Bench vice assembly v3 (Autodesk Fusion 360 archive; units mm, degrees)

design "Bench vice assembly" references "SCREW 2", "Base Plate"
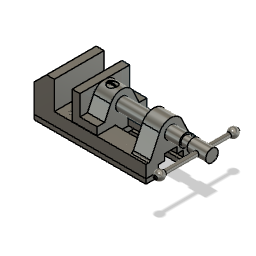
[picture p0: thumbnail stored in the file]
sketch "Sketch1" plane through (0, 0, 0) normal (0, 0, 1) x axis (1, 0, 0)
  line L1 (0, 36) -> (0, 0)
  line L2 (16, 52) -> (0, 36)
  line L3 (26, 52) -> (16, 52)
  line L4 (26, 16) -> (26, 52)
  line L5 (144, 16) -> (26, 16)
  line L6 (144, 0) -> (144, 16)
  line L7 (0, 0) -> (144, 0)
  point P1 (0, 0)
  point P2 (0, 0)
  point P10 (0, 0)
  point P7 (144, 16)
  point P8 (144, 16)
  point P9 (144, 0)
  point P4 (16, 52)
  point P5 (26, 52)
  point P3 (0, 36)
  coincident P1 P2
  vertical L1
  horizontal L3
  perpendicular L3 L4
  perpendicular L4 L5
  coincident P1 P10
  horizontal L7
  vertical L6
  coincident P7 P8
  dimension "d1" distance P9 P10 = 144
  dimension "d3" distance L5 L7 = 16
  dimension "d4" distance P4 P5 = 10
  dimension "d5" distance P3 P4 = 16
  dimension "d6" distance P3 P4 = 16
  dimension "d16" distance L3 L5 = 36
  dimension "d52" OffsetX = 0
  dimension "d53" OffsetY = 0
  dimension "d54" OffsetZ = 0
  dimension "d55" AngleZ = 0
  dimension "d43" OffsetX = 0
  dimension "d44" OffsetY = 0
  dimension "d45" OffsetZ = 0
  dimension "d46" AngleZ = 0
extrude "Extrude1" new body sketch "Sketch1" along normal blind 64 and against normal blind 0
sketch "Sketch2" plane through (144, 0, 0) normal (1, 0, 0) x axis (0, 0, -1)
  line L1 (0, 16) -> (0, 0)
  line L2 (-64, 16) -> (0, 16)
  line L3 (-64, 0) -> (-64, 16)
  line L4 (0, 0) -> (-64, 0)
  line L5 (-46.5009, 42.7619) -> (-58.9802, 16)
  line L6 (-5.0198, 16) -> (-17.4991, 42.7619)
  line L7 (-5.0198, 16) -> (-58.9802, 16)
  line L8 (-32, 59.4382) -> (-32, 0)
  arc A1 centre (-32, 36) radius 16 clockwise from (-46.5009, 42.7619) to (-17.4991, 42.7619)
  circle C1 centre (-32, 36) radius 8
  point P6 (-58.9802, 16)
  point P10 (-5.0198, 16)
  point P11 (-32, 0)
  point P9 (-32, 36)
  coincident L2 P6
  tangent L5 A1
  coincident L2 P10
  tangent A1 L6
  midpoint L4 P11
  perpendicular L4 L8
  symmetric L5 L6 L8
  concentric A1 C1
  dimension "d12" radius A1 = 16
  dimension "d13" angle L5 L6 = 50
  dimension "d14" distance L4 P9 = 36
  dimension "d15" diameter C1 = 16
extrude "Extrude2" add sketch "Sketch2" profile of L2 L5 A1 L6 L7 C1 against normal blind 22
fillet "Fillet1" radius 3
sketch "Sketch3" plane through (144, 0, 0) normal (1, 0, 0) x axis (0, 0, -1)
  line L1 (0, 16) -> (0, 0)
  line L2 (-3.1086, 16) -> (0, 16)
  line L3 (-17.4991, 42.7619) -> (-5.8275, 17.7321)
  line L4 (-58.1725, 17.7321) -> (-46.5009, 42.7619)
  line L5 (-64, 16) -> (-60.8914, 16)
  line L6 (-64, 0) -> (-64, 16)
  line L7 (0, 0) -> (-64, 0)
  line L8 (-48, 8) -> (-48, 0)
  line L9 (-40, 8) -> (-48, 8)
  line L10 (-64, 16) -> (0, 16)
  line L11 (-40, 16) -> (-40, 8)
  line L12 (-3.1086, 16) -> (-60.8914, 16)
  line L13 (-24, 8) -> (-24, 16)
  line L14 (-16, 8) -> (-24, 8)
  line L15 (-16, 0) -> (-16, 8)
  line L16 (-16, 0) -> (-48, 0)
  line L17 (-32, 74.8172) -> (-32, 0)
  line L18 (-24, 16) -> (-40, 16)
  circle C1 centre (-32, 36) radius 8
  arc A1 centre (-3.1086, 19) radius 3 clockwise from (-3.1086, 16) to (-5.8275, 17.7321)
  arc A2 centre (-32, 36) radius 16 clockwise from (-46.5009, 42.7619) to (-17.4991, 42.7619)
  arc A3 centre (-60.8914, 19) radius 3 clockwise from (-58.1725, 17.7321) to (-60.8914, 16)
  point P15 (-48, 0)
  point P20 (-40, 16)
  point P23 (-24, 16)
  point P26 (-16, 0)
  point P27 (-32, 0)
  coincident L7 P15
  perpendicular L7 L8
  perpendicular L8 L9
  coincident L10 P20
  perpendicular L7 L11
  coincident L10 P23
  perpendicular L10 L13
  perpendicular L13 L14
  coincident L7 P26
  midpoint L7 P27
  perpendicular L16 L17
  vertical L15
  symmetric L8 L15 L17
  symmetric L11 L13 L17
  dimension "d21" distance L11 L13 = 16
  dimension "d22" distance L8 L15 = 32
extrude "Extrude3" cut sketch "Sketch3" profile of L7 L8 L9 L10 L11 L12 L13 L14 L15 L16 L18 no distance stored
hole "Hole1" HoleDepth 10 HoleDiameter 6 TipAngle 118 RefDim1 10 RefDim2 36
hole "Hole3" HoleDepth 8 HoleDiameter 6 TipAngle 118
hole "Hole5" HoleDepth 10 HoleDiameter 6 TipAngle 118 RefDim1 38 RefDim2 10
sketch "Sketch5" plane through (0, 16, 0) normal (0, 1, 0) x axis (-1, 0, 0)
  line L1 (-122, 24) -> (-26, 24)
  line L2 (-122, 3.1086) -> (-122, 24)
  line L3 (-144, 3.1086) -> (-122, 3.1086)
  line L4 (-144, 0) -> (-144, 3.1086)
  line L5 (-26, 0) -> (-144, 0)
  line L6 (-26, 24) -> (-26, 0)
hole "Hole6" HoleDepth 8 HoleDiameter 6 TipAngle 118 RefDim1 38 RefDim2 10
ground "Ground1"
sketch "Sketch1" plane through (0, 0, 0) normal (0, 0, 1) x axis (1, 0, 0)
  line L1 (0, 10) -> (0, 0)
  line L2 (22, 10) -> (0, 10)
  line L3 (22, 36) -> (22, 10)
  line L4 (32, 36) -> (22, 36)
  line L5 (32, 0) -> (32, 36)
  line L6 (0, 0) -> (32, 0)
  point P1 (0, 0)
  point P2 (0, 0)
  point P3 (0, 10)
  point P5 (22, 36)
  point P6 (32, 36)
  coincident P1 P2
  vertical L1
  perpendicular L1 L2
  perpendicular L2 L3
  perpendicular L3 L4
  perpendicular L2 L5
  horizontal L6
  dimension "d1_1" distance P2 P3 = 10
  dimension "d2" distance P5 P6 = 10
  dimension "d3_1" distance L4 L6 = 36
  dimension "d4_1" distance L1 L5 = 32
  dimension "d30" OffsetX = 0
  dimension "d31" OffsetY = 0
  dimension "d41" OffsetZ = 0
  dimension "d42" AngleZ = 0
extrude "Extrude1" new body sketch "Sketch1" distance 64 named "d5_1"
sketch "Sketch2" plane through (0, 0, 32) normal (0, 0, 1) x axis (1, 0, 0)
  line L1 (32, 36) -> (32, 0)
  line L2 (22, 36) -> (32, 36)
  line L3 (22, 10) -> (22, 36)
  line L4 (0, 10) -> (22, 10)
  line L5 (0, 0) -> (0, 10)
  line L6 (32, 0) -> (0, 0)
sketch "Sketch3" plane through (0, 0, 0) normal (-1, 0, 0) x axis (0, 0, 1)
  line L1 (32, 0) -> (-32, 0)
  line L2 (32, 10) -> (32, 0)
  line L3 (-32, 0) -> (-32, 10)
  line L4 (-32, 10) -> (-32, 0)
  line L5 (-14.5009, 26.7619) -> (-22.3171, 10)
  line L6 (22.3171, 10) -> (14.5009, 26.7619)
  line L7 (32, 10) -> (22.3171, 10)
  line L8 (32, 10) -> (32, 0)
  line L9 (-32, 10) -> (-22.3171, 10)
  line L10 (32, 10) -> (-32, 10)
  line L11 (0, 44.7994) -> (0, 0)
  arc A1 centre (0, 20) radius 16 clockwise from (-14.5009, 26.7619) to (14.5009, 26.7619)
  point P3 (32, 0)
  point P15 (32, 0)
  point P2 (-32, 0)
  point P16 (-32, 0)
  point P8 (-22.3171, 10)
  point P12 (22.3171, 10)
  point P1 (0, 0)
  point P17 (0, 0)
  tangent L5 A1
  perpendicular L4 L9
  tangent A1 L6
  coincident P3 P15
  coincident P2 P16
  coincident P8 L10
  coincident P12 L10
  coincident P1 P17
  perpendicular L1 L11
  symmetric L5 L6 L11
  dimension "d7" angle L5 L6 = 50
  dimension "d8_1" radius A1 = 16
extrude "Extrude2" add sketch "Sketch3" profile of L5 A1 L6 L10 against normal blind 22 named "d9_1"
sketch "Sketch4" plane through (0, 0, 0) normal (-1, 0, 0) x axis (0, 0, 1)
  line L1 (32, 0) -> (-32, 0)
  line L2 (32, 10) -> (32, 0)
  line L3 (22.3171, 10) -> (32, 10)
  line L4 (14.5009, 26.7619) -> (22.3171, 10)
  line L5 (-22.3171, 10) -> (-14.5009, 26.7619)
  line L6 (-32, 10) -> (-22.3171, 10)
  line L7 (-32, 0) -> (-32, 10)
  line L8 (8, 0) -> (-8, 0)
  line L9 (8, -9) -> (8, 0)
  line L10 (-8, -9) -> (8, -9)
  line L11 (-8, 0) -> (-8, -9)
  line L12 (0, 61.8618) -> (0, 0)
  arc A1 centre (0, 20) radius 16 clockwise from (-14.5009, 26.7619) to (14.5009, 26.7619)
  point P11 (-8, 0)
  point P1 (0, 0)
  point P15 (0, 0)
  point P13 (8, -9)
  point P14 (-8, -9)
  horizontal L8
  vertical L9
  horizontal L10
  vertical L11
  coincident L1 P11
  coincident P1 P15
  vertical L12
  symmetric L9 L11 L12
  dimension "d11_1" distance P13 P14 = 16
  dimension "d12_1" distance L8 L10 = 9
extrude "Extrude3" add sketch "Sketch4" profile of L1 L8 L9 L10 L11 against normal blind 32 named "d13_1"
hole "Hole2" HoleDepth 16 HoleDiameter 6 named "d21_1" TipAngle 118 named "d22_1" RefDim1 8 named "d23_1" RefDim2 8
hole "Hole3" HoleDepth 16 HoleDiameter 6 TipAngle 118 RefDim1 8 RefDim2 8
sketch "Sketch5" plane through (0, 0, 0) normal (-1, 0, 0) x axis (0, 0, 1)
  line L1 (-8, 0) -> (-32, 0)
  line L2 (-8, -9) -> (-8, 0)
  line L3 (8, -9) -> (-8, -9)
  line L4 (8, 0) -> (8, -9)
  line L5 (32, 0) -> (8, 0)
  line L6 (32, 10) -> (32, 0)
  line L7 (22.3171, 10) -> (32, 10)
  line L8 (14.5009, 26.7619) -> (22.3171, 10)
  line L9 (-22.3171, 10) -> (-14.5009, 26.7619)
  line L10 (-32, 10) -> (-22.3171, 10)
  line L11 (-32, 0) -> (-32, 10)
  arc A1 centre (0, 20) radius 16 clockwise from (-14.5009, 26.7619) to (14.5009, 26.7619)
  circle C1 centre (0.9747, 18.2971) radius 9.9403
hole "Hole4" HoleDepth 24 HoleDiameter 12 TipAngle 118
hole "Hole5" HoleDepth 10 HoleDiameter 6 TipAngle 118 CBDepth 5 CBDiameter 12 RefDim1 20
work_axis "WorkAxis1"
work_point "WorkPoint1"
position "Position1"
joint "Assemble1" alignAngle 180 alignOffsetX 0 alignOffsetY 0 alignOffsetZ 0
sketch "Sketch1" plane through (0, 0, 0) normal (0, 0, 1) x axis (1, 0, 0)
  line L1 (6, 6) -> (0, 6)
  line L2 (6, 4) -> (6, 6)
  line L3 (15, 4) -> (6, 4)
  line L4 (15, 6) -> (15, 4)
  line L5 (22, 6) -> (15, 6)
  line L6 (22, 8) -> (22, 6)
  line L7 (104, 8) -> (22, 8)
  line L8 (104, 6) -> (104, 8)
  line L9 (114, 6) -> (104, 6)
  line L10 (114, 8) -> (114, 6)
  line L11 (138, 8) -> (114, 8)
  line L12 (138, 0) -> (138, 8)
  line L13 (0, 0) -> (138, 0)
  line L14 (0, 6) -> (0, 0)
  point P1 (0, 0)
  point P15 (0, 0)
  point P2 (0, 6)
  point P3 (6, 6)
  point P4 (6, 4)
  point P5 (15, 4)
  point P8 (22, 8)
  point P9 (104, 8)
  point P12 (114, 8)
  point P13 (138, 8)
  point P10 (104, 6)
  point P11 (114, 6)
  horizontal L1
  perpendicular L1 L2
  perpendicular L2 L3
  perpendicular L3 L4
  perpendicular L4 L5
  perpendicular L5 L6
  perpendicular L6 L7
  perpendicular L7 L8
  perpendicular L8 L9
  perpendicular L9 L10
  perpendicular L8 L11
  perpendicular L11 L12
  coincident P1 P15
  perpendicular L1 L14
  horizontal L13
  collinear L1 L5
  collinear L1 L9
  collinear L7 L11
  dimension "d1_2" = 12
  dimension "d2_1" = 8
  dimension "d3_2" distance P2 P3 = 6
  dimension "d4_2" distance P4 P5 = 9
  dimension "d5_2" distance P8 P9 = 82
  dimension "d6_2" distance P12 P13 = 24
  dimension "d7_1" distance P10 P11 = 10
  dimension "d8_2" = 16
  dimension "d9_2" distance L12 L14 = 138
revolve "Revolve1" sketch "Sketch1" AlongAngle 360 named "d10_2"
sketch "Sketch2" plane through (0, 0, 0) normal (0, 0, 1) x axis (1, 0, 0)
  line L1 (138, 8) -> (138, -8)
  line L2 (104, 6) -> (104, -6)
  line L3 (153.1035, 0) -> (0, 0)
  circle C1 centre (126, 0) radius 3
  point P1 (0, 0)
  point P7 (0, 0)
  point P2 (126, 0)
  coincident P1 P7
  perpendicular L2 L3
  coincident P2 L3
  dimension "d11_2" distance P2 L1 = 12
  dimension "d12_2" diameter C1 = 6
extrude "Extrude2" cut sketch "Sketch2" profile of C1 distance 15 named "d15_1"
position "Position2"
joint "Assemble2" alignAngle 180 alignOffsetX 0 alignOffsetY 0 alignOffsetZ 0
extrude "Extrude1" cut sketch "Sketch2" profile of C1 distance 12 named "d13_2"
position "Position3"
joint "Assemble3" alignAngle 180 alignOffsetX 0 alignOffsetY 0 alignOffsetZ 0
sketch "Sketch1" plane through (0, 0, 0) normal (0, 1, 0) x axis (1, 0, 0)
  circle C1 centre (0, 0) radius 3
  point P1 (0, 0)
  point P2 (0, 0)
  coincident P1 P2
  dimension "d1_3" diameter C1 = 6
extrude "Extrude1" new body sketch "Sketch1" along normal blind 8 named "d2_2"
sketch "Sketch2" plane through (0, 0, 0) normal (1, 0, 0) x axis (0, 0, -1)
  line L1 (0, 0) -> (0, 14.0504)
  line L2 (6, 8) -> (6, 11.35)
  line L3 (0, 8) -> (0, 12.6)
  line L4 (6, 8) -> (0, 8)
  line L5 (-3, 8) -> (3, 8)
  arc A1 centre (0, -2.425) radius 15.025 clockwise from (0, 12.6) to (6, 11.35)
  point P1 (0, 0)
  point P3 (0, 0)
  point P4 (0, 12.6)
  point P7 (0, -2.425)
  point P8 (0, 8)
  point P9 (0, 8)
  point P6 (6, 8)
  point P5 (6, 11.35)
  vertical L1
  coincident P1 P3
  vertical L2
  coincident L1 P4
  coincident L1 P7
  coincident P8 P9
  coincident P6 L5
  dimension "d4_3" distance P4 P5 = 1.25
  dimension "d5_3" distance P4 P6 = 4.6
  dimension "d6_3" = 12
revolve "Revolve1" sketch "Sketch2" AlongAngle 360 named "d7_2"
sketch "Sketch3" plane through (0, 0, 0) normal (1, 0, 0) x axis (0, 0, -1)
  line L1 (6, 11.35) -> (-6, 11.35)
  line L2 (-0.95, 10.7) -> (-0.95, 14.1051)
  line L3 (0.95, 10.7) -> (-0.95, 10.7)
  line L4 (0.95, 14.1051) -> (0.95, 10.7)
  line L5 (-0.95, 14.1051) -> (0.95, 14.1051)
  line L6 (0, 19.0294) -> (0, 8)
  point P8 (0, 8)
  point P9 (0, 8)
  point P4 (-0.95, 14.1051)
  point P7 (0.95, 14.1051)
  perpendicular L1 L2
  perpendicular L2 L3
  perpendicular L1 L4
  horizontal L5
  coincident P8 P9
  perpendicular L1 L6
  symmetric L2 L4 L6
  dimension "d8_3" distance P4 P7 = 1.9
  dimension "d9_3" distance L1 L3 = 0.65 (= "1.9 mm - 1.25 mm")
extrude "Extrude2" cut sketch "Sketch3" profile of L1 L2 L4 L5 distance -6 named "d10_3"
chamfer "Chamfer1" distance 1 named "d12_3"
joint "Assemble4" alignAngle 180 alignOffsetX 0 alignOffsetY 0 alignOffsetZ 0
sketch "Sketch1" plane through (0, 0, 0) normal (0, 0, 1) x axis (1, 0, 0)
  line L1 (0, 0) -> (-104, 0)
  line L2 (-104, 2) -> (-104, 0)
  line L3 (-94, 2) -> (-104, 2)
  line L4 (-94, 3) -> (-94, 2)
  line L5 (-10, 3) -> (-94, 3)
  line L6 (-10, 2) -> (-10, 3)
  line L7 (0, 2) -> (-10, 2)
  line L8 (0, 2) -> (0, 0)
  point P1 (0, 0)
  point P9 (0, 2)
  point P10 (0, 2)
  point P4 (-104, 2)
  point P5 (-94, 2)
  point P8 (-10, 2)
  horizontal L1
  coincident P1 L1
  perpendicular L1 L2
  perpendicular L2 L3
  perpendicular L3 L4
  perpendicular L4 L5
  perpendicular L5 L6
  perpendicular L6 L7
  perpendicular L1 L8
  coincident P9 P10
  collinear L3 L7
  coincident P1 L8
  dimension "d1_4" distance P4 P5 = 10
  dimension "d2_3" distance P8 P9 = 10
  dimension "d3_4" distance L2 L8 = 104
  dimension "d4_4" = 6
  dimension "d5_4" = 4
revolve "Revolve1" sketch "Sketch1" AlongAngle 360 named "d6_4"
joint "Assemble5" alignAngle 0 alignOffsetX 0 alignOffsetY 0 alignOffsetZ 0
sketch "Sketch1" plane through (0, 0, 0) normal (0, 0, 1) x axis (1, 0, 0)
  line L1 (0, 6) -> (0, -6)
  arc A1 centre (0, 0) radius 6 clockwise from (0, 6) to (0, -6)
  point P5 (0, 0)
  point P1 (0, 0)
  point P2 (0, -6)
  point P4 (0, -6)
  coincident L1 P5
  vertical L1
  coincident P1 P5
  coincident P2 P4
  dimension "d1_5" radius A1 = 6
revolve "Revolve1" sketch "Sketch1" AlongAngle 360 named "d2_4"
sketch "Sketch2" plane through (0, 0, 0) normal (0, 0, 1) x axis (1, 0, 0)
  line L1 (4.6153, 5.5) -> (-4.4358, 5.5)
  line L2 (-4.4358, 7.9056) -> (-4.4358, 5.5)
  line L3 (4.6153, 7.9056) -> (-4.4358, 7.9056)
  line L4 (4.6153, 5.5) -> (4.6153, 7.9056)
  point P1 (0, 0)
  horizontal L1
  perpendicular L1 L2
  perpendicular L2 L3
  perpendicular L1 L4
  dimension "d3_5" distance P1 L1 = 5.5
extrude "Extrude1" cut sketch "Sketch2" distance 7 named "d4_5"
sketch "Sketch3" plane through (0, 0, 0) normal (0, 0, 1) x axis (1, 0, 0)
  line L1 (6.0203, -5.5) -> (-4.8816, -5.5)
  line L2 (-4.8816, -7.3195) -> (-4.8816, -5.5)
  line L3 (6.0203, -7.3195) -> (-4.8816, -7.3195)
  line L4 (6.0203, -5.5) -> (6.0203, -7.3195)
  point P1 (0, 0)
  horizontal L1
  perpendicular L1 L2
  perpendicular L2 L3
  perpendicular L1 L4
  dimension "d6_5" distance P1 L1 = 5.5
extrude "Extrude2" cut sketch "Sketch3" distance -11 named "d7_3"
hole "Hole2" HoleDepth 12 named "d14_3" HoleDiameter 4 named "d15_2" TipAngle 118 named "d16_2" CSDiameter 4.8 named "d17_1" CSAngle 60 named "d18_1"
sketch "Sketch1" plane through (0, 0, 0) normal (0, 0, 1) x axis (1, 0, 0)
  line L1 (0, 6) -> (0, -6)
  arc A1 centre (0, 0) radius 6 clockwise from (0, 6) to (0, -6)
  point P5 (0, 0)
  point P1 (0, 0)
  point P2 (0, -6)
  point P4 (0, -6)
  coincident L1 P5
  vertical L1
  coincident P1 P5
  coincident P2 P4
  dimension "d1_6" radius A1 = 6
revolve "Revolve1" sketch "Sketch1" AlongAngle 360 named "d2_5"
sketch "Sketch2" plane through (0, 0, 0) normal (0, 0, 1) x axis (1, 0, 0)
  line L1 (4.6153, 5.5) -> (-4.4358, 5.5)
  line L2 (-4.4358, 7.9056) -> (-4.4358, 5.5)
  line L3 (4.6153, 7.9056) -> (-4.4358, 7.9056)
  line L4 (4.6153, 5.5) -> (4.6153, 7.9056)
  point P1 (0, 0)
  horizontal L1
  perpendicular L1 L2
  perpendicular L2 L3
  perpendicular L1 L4
  dimension "d3_6" distance P1 L1 = 5.5
extrude "Extrude1" cut sketch "Sketch2" distance 7 named "d4_6"
sketch "Sketch3" plane through (0, 0, 0) normal (0, 0, 1) x axis (1, 0, 0)
  line L1 (6.0203, -5.5) -> (-4.8816, -5.5)
  line L2 (-4.8816, -7.3195) -> (-4.8816, -5.5)
  line L3 (6.0203, -7.3195) -> (-4.8816, -7.3195)
  line L4 (6.0203, -5.5) -> (6.0203, -7.3195)
  point P1 (0, 0)
  horizontal L1
  perpendicular L1 L2
  perpendicular L2 L3
  perpendicular L1 L4
  dimension "d6_6" distance P1 L1 = 5.5
extrude "Extrude2" cut sketch "Sketch3" distance -11 named "d7_4"
hole "Hole2" HoleDepth 12 named "d14_4" HoleDiameter 4 named "d15_3" TipAngle 118 named "d16_3" CSDiameter 4.8 named "d17_2" CSAngle 60 named "d18_2"
move "Move1"
joint "Assemble6" alignAngle 180 alignOffsetX 0 alignOffsetY 0 alignOffsetZ 0
joint "Assemble7" alignAngle 0 alignOffsetX 0 alignOffsetY 0 alignOffsetZ 0
sketch "Sketch1" plane through (0, 0, 0) normal (0, 1, 0) x axis (1, 0, 0)
  line L1 (-16, 16) -> (16, 16)
  line L2 (-16, -16) -> (-16, 16)
  line L3 (16, -16) -> (-16, -16)
  line L4 (16, 16) -> (16, -16)
  line L5 (-16, -16) -> (16, 16)
  line L6 (16, -16) -> (-16, 16)
  point P6 (0, 0)
  point P1 (0, 0)
  point P4 (-16, -16)
  point P5 (16, -16)
  perpendicular L1 L2
  parallel L1 L3
  parallel L2 L4
  horizontal L1
  coincident L5 P6
  coincident L6 P6
  coincident P1 P6
  dimension "d1_7" distance P4 P5 = 32
  dimension "d2_6" distance L1 L3 = 32
extrude "Extrude1" new body sketch "Sketch1" profile of L1 L2 L3 L4 along normal blind 7 named "d3_7"
hole "Hole1" HoleDepth 7 named "d5_7" HoleDiameter 6 named "d6_7" TipAngle 119 named "d7_5" CSDiameter 12 named "d8_6" CSAngle 90 named "d9_4"
hole "Hole2" HoleDepth 7 named "d12_4" HoleDiameter 6 named "d13_3" TipAngle 118 named "d14_5" CSDiameter 11.78 named "d15_4" CSAngle 90 named "d16_4" RefDim1 8 named "d17_3" RefDim2 16 named "d18_3"
joint "Assemble8" alignAngle 180 alignOffsetX 0 alignOffsetY 0 alignOffsetZ 0
position "Position4"
joint "Assemble9" alignAngle 180 alignOffsetX 0 alignOffsetY 0 alignOffsetZ 0
sketch "Sketch1" plane through (0, 0, 0) normal (0, 1, 0) x axis (1, 0, 0)
  circle C1 centre (0, 0) radius 3
  point P1 (0, 0)
  point P2 (0, 0)
  coincident P1 P2
  dimension "d1_8" diameter C1 = 6
extrude "Extrude1" new body sketch "Sketch1" along normal blind 14 named "d2_7"
sketch "Sketch2" plane through (0, 0, 0) normal (0, 0, 1) x axis (1, 0, 0)
  line L1 (-3, 14) -> (3, 14)
  line L2 (3, 14) -> (0, 14)
  line L3 (5.25, 16.25) -> (3, 14)
  line L4 (5.25, 17) -> (5.25, 16.25)
  line L5 (0, 17) -> (5.25, 17)
  line L6 (0, 17) -> (0, 14)
  point P4 (0, 14)
  point P5 (3, 14)
  point P2 (3, 14)
  point P6 (5.25, 16.25)
  midpoint L1 P4
  coincident L1 P5
  parallel L1 L2
  perpendicular L1 L4
  perpendicular L4 L5
  perpendicular L5 L6
  coincident P2 P5
  dimension "d4_8" distance P6 L5 = 0.75
  dimension "d5_8" distance L2 L5 = 3
  dimension "d6_8" = 10.5
revolve "Revolve1" sketch "Sketch2" AlongAngle 360 named "d7_6"
sketch "Sketch3" plane through (0, 0, 0) normal (0, 0, 1) x axis (1, 0, 0)
  line L1 (0.75, 17) -> (-0.75, 17)
  line L2 (0.75, 15.5) -> (0.75, 17)
  line L3 (-0.75, 15.5) -> (0.75, 15.5)
  line L4 (-0.75, 17) -> (-0.75, 15.5)
  line L5 (5.25, 17) -> (-5.25, 17)
  line L6 (-3, 14) -> (3, 14)
  line L7 (0, 0) -> (0, 21.6679)
  point P2 (-0.75, 17)
  point P1 (0, 0)
  point P11 (0, 0)
  horizontal L1
  vertical L2
  horizontal L3
  vertical L4
  coincident P2 L5
  perpendicular L6 L7
  coincident P1 P11
  symmetric L2 L4 L7
  dimension "d8_7" distance L2 L4 = 1.5
  dimension "d9_5" distance L3 L6 = 1.5
extrude "Extrude2" cut sketch "Sketch3" profile of L1 L2 L3 L4 L5 distance 7 named "d10_4"
sketch "Sketch4" plane through (0, 0, 0) normal (0, 0, 1) x axis (1, 0, 0)
  line L1 (-3, 0) -> (3, 0)
  line L2 (3, 0) -> (0, 0)
  line L3 (0, -1.7321) -> (3, 0)
  line L4 (0, 0) -> (0, -1.7321)
  point P1 (0, 0)
  point P4 (0, 0)
  point P5 (3, 0)
  point P7 (0, 0)
  coincident P1 P4
  coincident L1 P5
  parallel L1 L2
  coincident P1 P7
  perpendicular L2 L4
  dimension "d12_5" distance P4 P5 = 3
  dimension "d14_6" angle L3 L4 = 60
revolve "Revolve2" sketch "Sketch4" AlongAngle 360 named "d15_5"
joint "Assemble10" alignAngle 180 alignOffsetX 0 alignOffsetY 0 alignOffsetZ 0
sketch "Sketch1" plane through (0, 0, 0) normal (0, 1, 0) x axis (1, 0, 0)
  circle C1 centre (0, 0) radius 3
  point P1 (0, 0)
  point P2 (0, 0)
  coincident P1 P2
  dimension "d1_9" diameter C1 = 6
extrude "Extrude1" new body sketch "Sketch1" along normal blind 14 named "d2_8"
sketch "Sketch2" plane through (0, 0, 0) normal (0, 0, 1) x axis (1, 0, 0)
  line L1 (-3, 14) -> (3, 14)
  line L2 (3, 14) -> (0, 14)
  line L3 (5.25, 16.25) -> (3, 14)
  line L4 (5.25, 17) -> (5.25, 16.25)
  line L5 (0, 17) -> (5.25, 17)
  line L6 (0, 17) -> (0, 14)
  point P4 (0, 14)
  point P5 (3, 14)
  point P2 (3, 14)
  point P6 (5.25, 16.25)
  midpoint L1 P4
  coincident L1 P5
  parallel L1 L2
  perpendicular L1 L4
  perpendicular L4 L5
  perpendicular L5 L6
  coincident P2 P5
  dimension "d4_9" distance P6 L5 = 0.75
  dimension "d5_9" distance L2 L5 = 3
  dimension "d6_9" = 10.5
revolve "Revolve1" sketch "Sketch2" AlongAngle 360 named "d7_7"
sketch "Sketch3" plane through (0, 0, 0) normal (0, 0, 1) x axis (1, 0, 0)
  line L1 (0.75, 17) -> (-0.75, 17)
  line L2 (0.75, 15.5) -> (0.75, 17)
  line L3 (-0.75, 15.5) -> (0.75, 15.5)
  line L4 (-0.75, 17) -> (-0.75, 15.5)
  line L5 (5.25, 17) -> (-5.25, 17)
  line L6 (-3, 14) -> (3, 14)
  line L7 (0, 0) -> (0, 21.6679)
  point P2 (-0.75, 17)
  point P1 (0, 0)
  point P11 (0, 0)
  horizontal L1
  vertical L2
  horizontal L3
  vertical L4
  coincident P2 L5
  perpendicular L6 L7
  coincident P1 P11
  symmetric L2 L4 L7
  dimension "d8_8" distance L2 L4 = 1.5
  dimension "d9_6" distance L3 L6 = 1.5
extrude "Extrude2" cut sketch "Sketch3" profile of L1 L2 L3 L4 L5 distance 7 named "d10_5"
sketch "Sketch4" plane through (0, 0, 0) normal (0, 0, 1) x axis (1, 0, 0)
  line L1 (-3, 0) -> (3, 0)
  line L2 (3, 0) -> (0, 0)
  line L3 (0, -1.7321) -> (3, 0)
  line L4 (0, 0) -> (0, -1.7321)
  point P1 (0, 0)
  point P4 (0, 0)
  point P5 (3, 0)
  point P7 (0, 0)
  coincident P1 P4
  coincident L1 P5
  parallel L1 L2
  coincident P1 P7
  perpendicular L2 L4
  dimension "d12_6" distance P4 P5 = 3
  dimension "d14_7" angle L3 L4 = 60
revolve "Revolve2" sketch "Sketch4" AlongAngle 360 named "d15_6"
joint "Assemble11" alignAngle 180 alignOffsetX 0 alignOffsetY 0 alignOffsetZ 0
sketch "Sketch1" plane through (0, 0, 0) normal (0, 0, 1) x axis (1, 0, 0)
  line L1 (-72, 10) -> (72, 10)
  line L2 (-72, -10) -> (-72, 10)
  line L3 (72, -10) -> (-72, -10)
  line L4 (72, 10) -> (72, -10)
  line L5 (-72, -10) -> (72, 10)
  line L6 (72, -10) -> (-72, 10)
  point P6 (0, 0)
  point P1 (0, 0)
  point P4 (-72, -10)
  point P5 (72, -10)
  perpendicular L1 L2
  parallel L1 L3
  parallel L2 L4
  horizontal L1
  coincident L5 P6
  coincident L6 P6
  coincident P1 P6
  dimension "d1_10" distance P4 P5 = 144
  dimension "d2_9" distance L1 L3 = 20
extrude "Extrude1" new body sketch "Sketch1" profile of L1 L2 L3 L4 along normal blind 6 named "d3_10"
hole "Hole1" HoleDepth 12 named "d5_10" HoleDiameter 6 named "d6_10" TipAngle 118 named "d7_8" CSDiameter 10.5 named "d8_9" CSAngle 45 named "d9_7" RefDim1 35 named "d10_6" RefDim2 10 named "d11_6"
hole "Hole2" HoleDepth 12 named "d12_7" HoleDiameter 7 named "d13_4" TipAngle 118 named "d14_8" CSDiameter 10.5 named "d15_7" CSAngle 45 named "d16_5" RefDim1 10 named "d17_4" RefDim2 38 named "d18_4"
move "Move1"
joint "Assemble12" alignAngle 0 alignOffsetX 0 alignOffsetY 0 alignOffsetZ 0
component_insert "Component Insert1"
joint "Assemble13" alignAngle 0 alignOffsetX 0 alignOffsetY 0 alignOffsetZ 3
component_insert "Component Insert2"
joint "Assemble14" alignAngle 0 alignOffsetX 0 alignOffsetY 0 alignOffsetZ 2
component_insert "Component Insert3"
component_insert "Component Insert5"
joint "Assemble15" alignAngle 0 alignOffsetX -70 alignOffsetY 0 alignOffsetZ 0
joint "Assemble16" alignAngle 90 alignOffsetX 0 alignOffsetY 0 alignOffsetZ 0
component_insert "Component Insert6"
joint "Assemble17" alignAngle 0 alignOffsetX 0 alignOffsetY 0 alignOffsetZ 0
position "Position5"
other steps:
create_component "CreateComponent1"
create_component "CreateComponent2"
joint_origin "JointOrigin2" OffsetX 0 OffsetY 0 OffsetZ 0 AngleZ 0
joint_origin "JointOrigin9" OffsetX 0 OffsetY 0 OffsetZ 0 AngleZ 0
create_component "CreateComponent3"
joint_origin "JointOrigin1" OffsetX 0 OffsetY 0 OffsetZ 0 AngleZ 0
joint_origin "JointOrigin3" OffsetX 0 OffsetY 0 OffsetZ 0 AngleZ 0
joint_origin "JointOrigin2" OffsetX 0 OffsetY 0 OffsetZ 0 AngleZ 0
joint_origin "JointOrigin4" OffsetX 0 OffsetY 0 OffsetZ 0 AngleZ 0
create_component "CreateComponent4"
joint_origin "JointOrigin1" OffsetX 0 OffsetY 0 OffsetZ 0 AngleZ 0
joint_origin "JointOrigin5" OffsetX 0 OffsetY 0 OffsetZ 0 AngleZ 0
create_component "CreateComponent5"
joint_origin "JointOrigin1" OffsetX 0 OffsetY 0 OffsetZ 0 AngleZ 0
joint_origin "JointOrigin3" OffsetX 0 OffsetY 0 OffsetZ 0 AngleZ 0
create_component "CreateComponent6"
create_component "CreateComponent7"
joint_origin "JointOrigin1" OffsetX 0 OffsetY 0 OffsetZ 0 AngleZ 0
joint_origin "JointOrigin2" OffsetX 0 OffsetY 0 OffsetZ 0 AngleZ 0
joint_origin "JointOrigin1" OffsetX 0 OffsetY 0 OffsetZ 0 AngleZ 0
joint_origin "JointOrigin3" OffsetX 0 OffsetY 0 OffsetZ 0 AngleZ 0
create_component "CreateComponent8"
joint_origin "JointOrigin1" OffsetX 0 OffsetY 0 OffsetZ 0 AngleZ 0
joint_origin "JointOrigin6" OffsetX 0 OffsetY 0 OffsetZ 0 AngleZ 0
joint_origin "JointOrigin7" OffsetX 0 OffsetY 0 OffsetZ 0 AngleZ 0
joint_origin "JointOrigin2" OffsetX 0 OffsetY 0 OffsetZ 0 AngleZ 0
create_component "CreateComponent9"
joint_origin "JointOrigin1" OffsetX 0 OffsetY 0 OffsetZ 0 AngleZ 0
joint_origin "JointOrigin3" OffsetX 0 OffsetY 0 OffsetZ 0 AngleZ 0
create_component "CreateComponent10"
joint_origin "JointOrigin1" OffsetX 0 OffsetY 0 OffsetZ 0 AngleZ 0
joint_origin "JointOrigin4" OffsetX 0 OffsetY 0 OffsetZ 0 AngleZ 0
create_component "CreateComponent11"
joint_origin "JointOrigin1" OffsetX 0 OffsetY 0 OffsetZ 0 AngleZ 0
joint_origin "JointOrigin10" OffsetX 0 OffsetY 0 OffsetZ 0 AngleZ 0
joint_origin "JointOrigin3"
joint_origin "JointOrigin5"
joint_origin "JointOrigin11"

design "Base Plate"
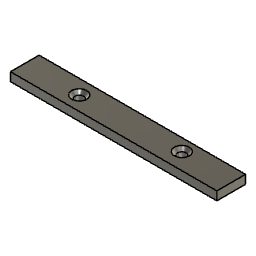
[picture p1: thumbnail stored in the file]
sketch "Sketch1" plane through (0, 0, 0) normal (0, 0, 1) x axis (1, 0, 0)
  line L1 (-72, 10) -> (72, 10)
  line L2 (-72, -10) -> (-72, 10)
  line L3 (72, -10) -> (-72, -10)
  line L4 (72, 10) -> (72, -10)
  line L5 (-72, -10) -> (72, 10)
  line L6 (72, -10) -> (-72, 10)
  point P6 (0, 0)
  point P1 (0, 0)
  point P4 (-72, -10)
  point P5 (72, -10)
  point P3 (-72, 10)
  horizontal L1
  perpendicular L1 L2
  parallel L1 L3
  parallel L2 L4
  coincident L5 P6
  coincident L6 P6
  coincident P1 P6
  dimension "d1" distance P4 P5 = 144
  dimension "d2" distance P3 P4 = 20
extrude "Extrude1" new body sketch "Sketch1" profile of L1 L2 L3 L4 along normal blind 6
sketch "Sketch2" plane through (0, 0, 0) normal (0, 1, 0) x axis (1, 0, 0)
  line L1 (-34, -6) -> (-34, 0)
  line L2 (-28.75, -6) -> (-34, -6)
  line L3 (-31, -3.75) -> (-28.75, -6)
  line L4 (-31, 0) -> (-31, -3.75)
  line L5 (-34, 0) -> (-31, 0)
  line L6 (72, 0) -> (-72, 0)
  line L7 (72, -6) -> (-72, -6)
  line L8 (-34, -17.0871) -> (-34, -6)
  point P6 (-31, 0)
  point P4 (-28.75, -6)
  point P7 (-72, 0)
  vertical L1
  perpendicular L1 L2
  perpendicular L2 L4
  perpendicular L1 L5
  coincident P6 L6
  coincident P4 L7
  perpendicular L2 L8
  dimension "d5" distance L1 P7 = 38
  dimension "d6" = 10.5
  dimension "d7" distance L1 L4 = 3
  dimension "d8" angle L3 L8 = 45
revolve "Revolve1" sketch "Sketch2" AlongAngle 360
hole "Hole1" sketch "Sketch2" HoleDepth 20 HoleDiameter 6 TipAngle 45 CSDiameter 10.5 CSAngle 90 RefDim1 108

design "SCREW 2"
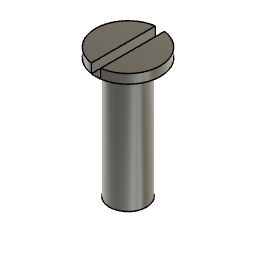
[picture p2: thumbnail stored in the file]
sketch "Sketch1" plane through (0, 0, 0) normal (0, 1, 0) x axis (1, 0, 0)
  line L1 (0, -69.9357) -> (0, 0)
  line L2 (5.25, -22.7321) -> (0, -22.7321)
  line L3 (0, 0) -> (0, -22.7321)
  line L4 (5.25, -21.2321) -> (5.25, -22.7321)
  line L5 (0, 0) -> (3, -1.7321)
  line L6 (-71.0977, 0) -> (0, 0)
  line L7 (3, -1.7321) -> (3, -19.7321)
  line L8 (3, -19.7321) -> (5.25, -21.2321)
  point P3 (0, 0)
  point P4 (0, 0)
  point P7 (0, 0)
  point P11 (0, -22.7321)
  point P6 (0, 0)
  point P2 (0, 0)
  point P1 (0, 0)
  point P8 (3, -19.7321)
  point P12 (3, -1.7321)
  point P5 (5.25, -22.7321)
  point P13 (5.25, -21.2321)
  coincident P3 P4
  coincident P3 P7
  perpendicular L1 L6
  coincident P11 L1
  perpendicular L1 L2
  perpendicular L2 L4
  perpendicular L2 L7
  coincident P3 P6
  coincident P2 P3
  coincident P1 P2
  vertical L1
  dimension "d3" distance L1 L7 = 3
  dimension "d5" angle L3 L5 = 60
  dimension "d12" distance P8 P12 = 18
  dimension "d13" distance P5 P13 = 1.5
  dimension "d14" distance P8 L2 = 3
  dimension "d15" distance L1 L4 = 5.25
revolve "Revolve1" sketch "Sketch1" AlongAngle 360
sketch "Sketch2" plane through (0, 0, 0) normal (0, 1, 0) x axis (1, 0, 0)
  line L1 (0.75, -27.3977) -> (-0.75, -27.3977)
  line L2 (0.75, -21.2321) -> (0.75, -27.3977)
  line L3 (-0.75, -21.2321) -> (0.75, -21.2321)
  line L4 (-0.75, -27.3977) -> (-0.75, -21.2321)
  line L5 (0, -33.7632) -> (0, 0)
  line L6 (5.25, -22.7321) -> (-5.25, -22.7321)
  point P1 (0, 0)
  point P6 (0, 0)
  point P4 (0.75, -21.2321)
  point P5 (-0.75, -21.2321)
  horizontal L1
  vertical L2
  horizontal L3
  vertical L4
  coincident P1 P6
  vertical L5
  symmetric L2 L4 L5
  dimension "d8" distance P4 P5 = 1.5
  dimension "d9" distance L3 L6 = 1.5
extrude "Extrude1" cut sketch "Sketch2" profile of L1 L2 L3 L4 L6 distance 7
